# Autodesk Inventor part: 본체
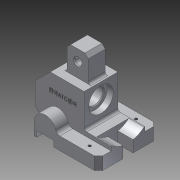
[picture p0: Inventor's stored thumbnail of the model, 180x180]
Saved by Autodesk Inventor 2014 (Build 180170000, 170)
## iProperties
Created: 2016-11
Part Number: 본체
Material: Aluminum 6061
Document SubType Name: Modeling
Designer: user
Density: 2.71 g/cm^3
Appearance: Aluminum - Flat
Mass: 462.906 g
Surface Area: 317.29 cm^2
Volume: 170.814 cm^3
Author: user
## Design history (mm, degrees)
sketch "Sketch1"
  geometry: L1 (-13, 35)-(63, 35); L2 (63, 35)-(63, -35); L3 (63, -35)-(-13, -35); L4 (-13, -35)-(-13, 35); L5 (63, 0)-(-13, 0); L6 (0, 35)-(0, -35); 2 further points
  constraints: 12 end point, 3 midpoint, 2 parallel, 2 perpendicular, 2 point on line, 1 coincident, 1 horizontal
  dimensions: "d0" = 70 distance of L1.end L2.end; "d1" = 63 distance between parallel lines of L2 L6; "d2" = 13 distance between parallel lines of L4 L6
extrude "Extrusion1" new body sketch "Sketch1" distance "d3" = 15; taper "d4" = 0 deg
sketch "Sketch2"
  geometry: L1 (0, 15)-(76, 15) reference; L2 (0, 0)-(0, 15) reference; L3 (13, 0)-(13, 15); C1 r 13 at (13, 15)
  constraints: 2 end point, 1 centre point, 1 coincident, 1 parallel, 1 point on line
  dimensions: "d5" = 26 diameter of C1
extrude "Extrusion2" join sketch "Sketch2" distance "d6" = 70; taper "d7" = 0 deg
sketch "Sketch3"
  geometry: L1 (76, 0)-(0, 0) reference; L2 (3, 7)-(23, 7); L3 (23, 7)-(23, -7.564); L4 (23, -7.564)-(3, -7.564); L5 (3, -7.564)-(3, 7); 2 further points
  constraints: 8 end point, 2 parallel, 1 horizontal, 1 midpoint, 1 perpendicular, 1 vertical alignment
  dimensions: "d8" = 20 distance between parallel lines of L3 L5; "d9" = 7 distance between parallel lines of L1 L2
extrude "Extrusion3" cut sketch "Sketch3" distance "d10" = 70; taper "d11" = 0 deg
workplane "Work Plane1"
sketch "Sketch4"
  geometry: L1 (-31, -20)-(27, -20); L2 (27, -20)-(27, 20); L3 (27, 20)-(-31, 20); L4 (-31, 20)-(-31, -20); L5 (-63, -35)-(-63, 35) reference; 2 further points
  constraints: 8 end point, 2 parallel, 1 horizontal, 1 horizontal alignment, 1 midpoint, 1 perpendicular
  dimensions: "d13" = 40 distance of L3.end L1.start; "d14" = 32 distance between parallel lines of L5 L4; "d15" = 58 distance of L2.end L3.end
extrude "Extrusion4" join sketch "Sketch4" distance "d16" = 48; taper "d17" = 0 deg
fillet "Fillet2" dims "d22" = 5
chamfer "Chamfer2" distance "d23" = 4; stored, may be unused: second distance "d24" = 2, angle "d25" = 45 deg
sketch "Sketch5"
  geometry: L1 (31, 20)-(31, -20) reference; L2 (63, -35)-(63, 35) reference; L3 (31, 20)-(63, 20); L4 (63, 20)-(63, -20); L5 (63, -20)-(31, -20); L6 (31, -20)-(31, 20); 3 further points
  constraints: 8 end point, 2 collinear, 2 midpoint, 2 parallel, 1 coincident, 1 horizontal, 1 perpendicular
  dimensions: "d26" = 40 distance between parallel lines of L5 L3
extrude "Extrusion5" join sketch "Sketch5" distance "d27" = 5; taper "d28" = 0 deg
sketch "Sketch6"
  geometry: L1 (0, 0)-(58, 0) reference; L2 (0, -44)-(0, 0) reference; L3 (18, 0)-(0, -18); 1 further point
  constraints: 2 end point, 2 point on line
  dimensions: "d29" = 18 distance of L1.start L3.start; "d30" = 45 deg angle of L3 L1
extrude "Extrusion6" cut sketch "Sketch6" distance "d31" = 50; taper "d32" = 0 deg
sketch "Sketch7"
  geometry: L1 (31, -20)-(31, 20) reference; L2 (1, 10)-(26, 10); L3 (26, 10)-(26, -10); L4 (26, -10)-(1, -10); L5 (1, -10)-(1, 10); 3 further points
  constraints: 8 end point, 2 midpoint, 2 parallel, 1 horizontal, 1 horizontal alignment, 1 perpendicular
  dimensions: "d33" = 20 distance of L2.end L3.end; "d34" = 5 distance between parallel lines of L1 L3; "d35" = 25 distance of L3.end L4.end
extrude "Extrusion7" join sketch "Sketch7" distance "d36" = 30; taper "d37" = 0 deg
chamfer "Chamfer3" distance "d38" = 4; stored, may be unused: second distance "d39" = 2, angle "d40" = 45 deg
fillet "Fillet3" dims "d41" = 3
sketch "Sketch8"
  geometry: L1 (-4, -27)-(-4, -4) reference; L2 (58, -90)-(5, -90) reference; 2 further points
  dimensions: "d42" = 77 distance from line of L2 point (8.5, -13); "d43" = 12.5 distance from line of point (8.5, -13) L1
hole "Hole1" sketch "Sketch8" at (8.5, -13) diameter "d44" = 8; stored, may be unused: countersink angle "d48" = 90 deg, drill point angle "d50" = 0 deg; dims "d45" = 6, "d46" = 4, "d47" = 2, "d49" = 8
chamfer "Chamfer4" distance "d51" = 1; stored, may be unused: second distance "d52" = 2, angle "d53" = 45 deg
sketch "Sketch9"
  geometry: L1 (60, 55)-(60, -15) reference; 3 further points
  constraints: 1 horizontal alignment, 1 midpoint
  dimensions: "d54" = 42 distance from line of L1 point (18, 20)
hole "Hole2" sketch "Sketch9" at (18, 20) diameter "d55" = 20; stored, may be unused: countersink angle "d59" = 90 deg, drill point angle "d61" = 0 deg; dims "d56" = 6, "d57" = 29, "d58" = 7, "d60" = 8
chamfer "Chamfer5" distance "d62" = 1; stored, may be unused: second distance "d63" = 2, angle "d64" = 45 deg
sketch "Sketch10"
  geometry: C1 r 14.5 at (-42, 35) reference; C2 r 29 at (-42, 35); 1 further point
  constraints: 1 centre point, 1 coincident
  dimensions: "d65" = 29 radius of C2
extrude "Extrusion8" cut sketch "Sketch10" distance "d66" = 18; taper "d67" = 0 deg
sketch "Sketch11"
  geometry: L1 (-63, 35)-(-63, -35) reference; L2 (-63, 6)-(-45, 6); L3 (-45, 6)-(-45, -6); L4 (-45, -6)-(-63, -6); L5 (-63, -6)-(-63, 6); 3 further points
  constraints: 8 end point, 2 midpoint, 2 parallel, 1 coincident, 1 collinear, 1 horizontal, 1 perpendicular
  dimensions: "d68" = 12 distance between parallel lines of L4 L2; "d69" = 18 distance of L2.start L2.end
extrude "Extrusion9" cut sketch "Sketch11" distance "d70" = 18; taper "d71" = 0 deg
fillet "Fillet4" dims "d72" = 3
chamfer "Chamfer6" distance "d73" = 5; stored, may be unused: second distance "d74" = 2, angle "d75" = 45 deg
sketch "Sketch12"
  geometry: L1 (63, -30)-(63, -20) reference; L2 (34, -20)-(34, 20) reference; L3 (34, -20)-(63, -20) reference; L4 (63, -20)-(63, -18.894) reference; L5 (63, -18.894)-(45, -18.894) reference; L6 (45, -18.894)-(45, 18.894) reference; L7 (45, 18.894)-(63, 18.894) reference; L8 (63, 18.894)-(63, 20) reference; L9 (63, 20)-(34, 20) reference; L10 (10, -35)-(10, 35) reference; L11 (-2, 10)-(29, 10) reference; L12 (29, -10)-(29, 10) reference; L13 (29, -10)-(-2, -10) reference; L14 (-2, 10)-(-2, -10) reference; L15 (-9, 20)-(-9, -20) reference; L16 (-9, -20)-(31, -20) reference; L17 (31, -20)-(31, 20) reference; L18 (31, 20)-(-9, 20) reference; A1 r 10 centre (-27, 0) between (-27, -10) and (-27, 10) reference; 3 further points
  constraints: 1 vertical alignment
  dimensions: "d76" = 55 distance of point (45, -27.5) point (45, 27.5); "d77" = 18 distance from line of point (45, -27.5) L1; "d78" = 27.5 vertical distance of point (45, 27.5) point (0, 0)
hole "Hole3" sketch "Sketch12" at (45, 27.5), (45, -27.5) diameter "d79" = 3.242; stored, may be unused: countersink angle "d83" = 90 deg, drill point angle "d85" = 0 deg; dims "d80" = 15, "d81" = 29, "d82" = 7, "d84" = 8
sketch "Sketch13"
  geometry: L1 (44, 11)-(44, 48) reference; L2 (4, 48)-(44, 48) reference; 3 further points
  constraints: 1 coincident, 1 other
  dimensions: "d86" = 18 distance from line of L2 point (19, 30); "d87" = 25 distance from line of L1 point (19, 30)
emboss "Emboss1" sketch "Sketch13" dims "d0" = 70, "d1" = 63, "d2" = 13, "d88" = 0.5, "d89" = 0
body "Solid1"
node "Projected Loop1"
node "Projected Loop2"
other parameters: "d12" = -12
